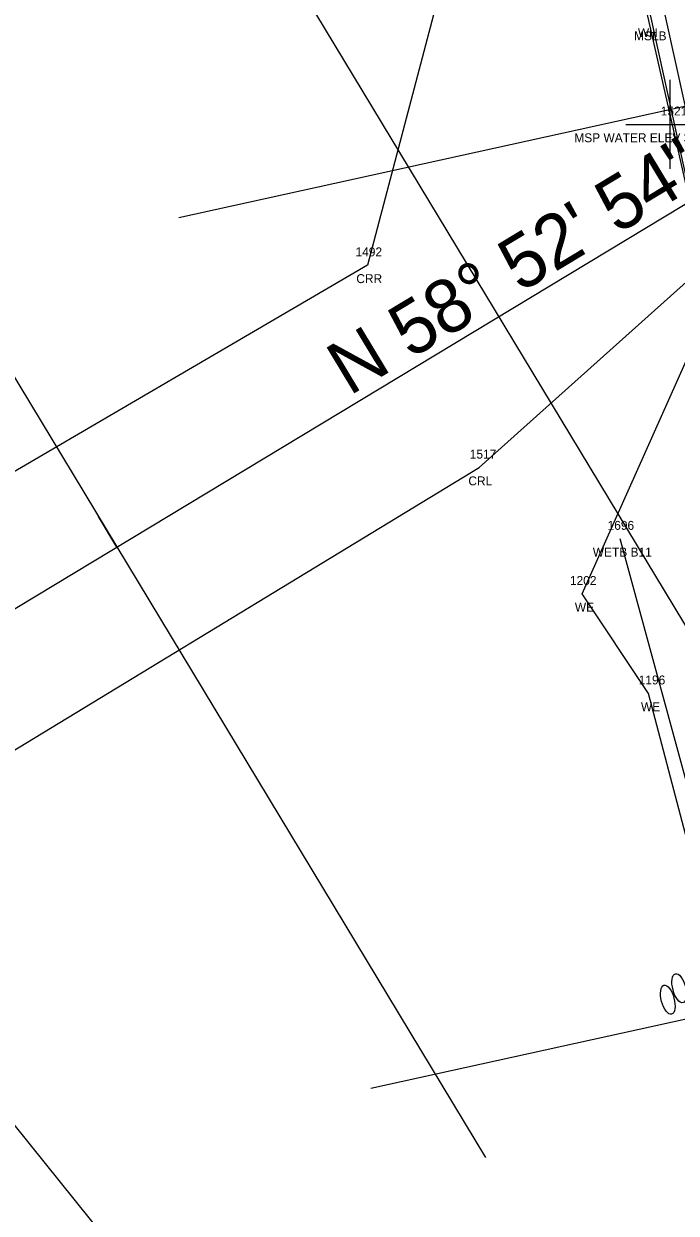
# Model space of a CAD drawing. Extents: x 2522090 to 2524658, y 882711 to 887512.
# Drawn here: x 2523693.6 to 2523766.8, y 884993.3 to 885126.7 of the extents above; entities that cross this region are included whole.
import ezdxf

# ---------------------------------------------------------------- set-up
doc = ezdxf.new("R2010")
doc.units = 0
for name, color, linetype in [('RD_EV_JurisArea', 7, 'Continuous'), ('RD_EX_BldgApp', 7, 'Continuous'), ('RD_EX_BldgApp_txCode', 7, 'Continuous'), ('RD_EX_Bridge', 7, 'Continuous'), ('RD_EX_H2O', 7, 'Continuous'), ('RD_EX_H2O_txCode', 7, 'Continuous'), ('RD_EX_H2O_WetLd_txCode', 7, 'Continuous'), ('RD_EX_Misc', 7, 'Continuous'), ('RD_EX_Misc_txCode', 7, 'Continuous'), ('RD_HC_Cl', 7, 'Continuous'), ('RD_HC_Data', 7, 'Continuous'), ('RD_HC_Data_Tic', 7, 'Continuous'), ('RD_PD_Bridge', 7, 'Continuous'), ('RD_PD_PatLn5', 7, 'Continuous'), ('RD_PD_PatLn6', 7, 'Continuous'), ('RD_PD_PaveShd', 7, 'Continuous'), ('RD_SMD_Locator', 7, 'Continuous')]:
    doc.layers.add(name, color=color, linetype=linetype)

msp = doc.modelspace()

# ---------------------------------------------------------------- linework, layer by layer
at = {"layer": 'RD_EV_JurisArea'}
msp.add_lwpolyline([(2523827.75, 884469.64), (2523867.43, 884517.67), (2523885.95, 884534.84), (2523882.77, 884582.72), (2523847.74, 884736.42), (2523822.93, 884833.79), (2523804.26, 884914.89), (2523780.91, 884992.76), (2523770.73, 885031.48), (2523760.5, 885068.9)], dxfattribs=at)
at = {"layer": 'RD_EX_BldgApp'}
msp.add_lwpolyline([(2523776.68, 885077.92), (2523768.27, 885115.31), (2523760.2, 885151.9)], dxfattribs=at)
at = {"layer": 'RD_EX_Bridge'}
msp.add_lwpolyline([(2523774.91, 885077.6), (2523821.2, 885087.83), (2523805.06, 885161.89), (2523758.15, 885151.44), (2523774.91, 885077.6)], dxfattribs=at)
at = {"layer": 'RD_EX_H2O'}
for points in [[(2523582.82, 884766.34), (2523598.11, 884856.98), (2523627.59, 884901.75), (2523623.76, 884928.28), (2523586.58, 884955.43), (2523600.94, 884974.12), (2523633.05, 884997.68), (2523679.17, 885037.05), (2523744.72, 885076.89), (2523769.38, 885099), (2523825.47, 885108.66), (2523825.47, 885108.66), (2523845.24, 885110.83), (2523890.25, 885154.93), (2523858.43, 885178.04), (2523850.81, 885196.93), (2523892.51, 885249.74), (2523936.89, 885290.09), (2523980.86, 885285.47), (2524009.06, 885269.77), (2524037.39, 885280.09)], [(2523741.75, 885135.92), (2523732.18, 885099.57), (2523664.9, 885060.26), (2523614.86, 885022.02), (2523558.95, 884972.63), (2523560.62, 884942.42), (2523490.01, 884911.76)], [(2523792.73, 884941.12), (2523763.67, 885051.56), (2523756.26, 885062.72), (2523770.47, 885094.55), (2523817.57, 885105.71), (2523827.83, 885106)]]:
    msp.add_lwpolyline(points, dxfattribs=at)
at = {"layer": 'RD_EX_Misc'}
for p, q in [((2523766.13, 885110.37), (2523766.13, 885120.37)), ((2523761.13, 885115.37), (2523771.13, 885115.37))]:
    msp.add_line(p, q, dxfattribs=at)
at = {"layer": 'RD_HC_Cl'}
msp.add_line((2523672.04, 885048.63), (2523837.18, 885148.32), dxfattribs=at)
at = {"layer": 'RD_HC_Data_Tic'}
msp.add_line((2523704.08, 885067.97), (2523702.01, 885071.4), dxfattribs=at)
at = {"layer": 'RD_PD_Bridge'}
msp.add_lwpolyline([(2523748.47, 885197.62), (2523785.03, 885031.6)], dxfattribs=at)
at = {"layer": 'RD_PD_PatLn5'}
for p, q in [((2523877.06, 885141.45), (2523711.04, 885104.9)), ((2523888.8, 885041.64), (2523732.54, 885007.24))]:
    msp.add_line(p, q, dxfattribs=at)
at = {"layer": 'RD_PD_PatLn6'}
for p, q in [((2523705.54, 885162.3), (2523788.23, 885025.33)), ((2523662.74, 885136.46), (2523745.43, 884999.49)), ((2523612.04, 885103.02), (2523712.47, 884978.46))]:
    msp.add_line(p, q, dxfattribs=at)
at = {"layer": 'RD_PD_PaveShd'}
for centre in [(2523767.13, 885018.49), (2523767.13, 885018.49), (2523765.85, 885017.2), (2523765.85, 885017.2)]:
    msp.add_ellipse(centre, major_axis=(0.43, -1.62), ratio=0.429445, dxfattribs=at)
at = {"layer": 'RD_SMD_Locator'}
for centre in [(2523732.18, 885099.57), (2523744.72, 885076.89), (2523760.5, 885068.9), (2523756.26, 885062.72), (2523763.67, 885051.56)]:
    msp.add_circle(centre, 0.001, dxfattribs=at)

# ---------------------------------------------------------------- texts
at = {"layer": 'RD_EX_BldgApp_txCode'}
msp.add_text('WH', height=1, dxfattribs=at).set_placement((2523762.5, 885125.16))
at = {"layer": 'RD_EX_H2O_txCode'}
for s, p in [('1492', (2523730.84, 885100.57)), ('CRR', (2523730.93, 885097.57)), ('1517', (2523743.65, 885077.89)), ('CRL', (2523743.49, 885074.89)), ('1202', (2523754.88, 885063.72)), ('WE', (2523755.43, 885060.72)), ('1196', (2523762.59, 885052.56)), ('WE', (2523762.84, 885049.56))]:
    msp.add_text(s, height=1, dxfattribs=at).set_placement(p)
at = {"layer": 'RD_EX_H2O_WetLd_txCode'}
for s, p in [('1696', (2523759.1, 885069.9)), ('WETB B11', (2523757.44, 885066.9))]:
    msp.add_text(s, height=1, dxfattribs=at).set_placement(p)
at = {"layer": 'RD_EX_Misc_txCode'}
for s, p in [('MSLB', (2523762.07, 885124.8)), ('1521', (2523765.06, 885116.37)), ('MSP WATER ELEV 3-26-2014', (2523755.37, 885113.37))]:
    msp.add_text(s, height=1, dxfattribs=at).set_placement(p)
at = {"layer": 'RD_HC_Data'}
msp.add_text('N 58%%d 52\' 54" E', height=6, rotation=31.1184, dxfattribs=at).set_placement((2523730.14, 885084.87))

doc.saveas('drawing.dxf')
